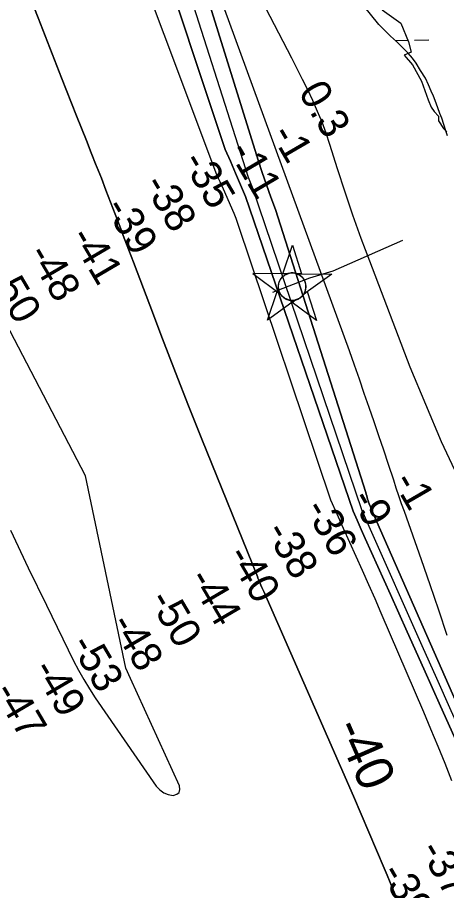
# Model space of a CAD drawing. Extents: x 3914892 to 3953151, y 242587 to 268572.
# Drawn here: x 3942793 to 3943744, y 249840 to 251778 of the extents above; entities that cross this region are included whole.
import ezdxf

# ---------------------------------------------------------------- set-up
doc = ezdxf.new("R2010")
doc.units = 0
for name, color, linetype in [('V-CHAN-NAID', 7, 'Continuous'), ('V-LEVE-TOET', 7, 'Continuous'), ('V-RIVR-EDGE', 7, 'Continuous'), ('V-RIVR-RANG', 7, 'Continuous'), ('V-TOPO-DPTH', 7, 'Continuous'), ('V-TOPO-MAJR', 7, 'Continuous'), ('V-TOPO-MAJR-IDEN', 7, 'Continuous'), ('V-TOPO-MINR', 7, 'Continuous'), ('V-TOPO-WATR', 7, 'Continuous'), ('V-WETL-SWMP', 7, 'Continuous')]:
    doc.layers.add(name, color=color, linetype=linetype)

msp = doc.modelspace()

# ---------------------------------------------------------------- linework, layer by layer
at = {"layer": 'V-CHAN-NAID'}
for points in [[(3943390.8, 251209), (3943381.2, 251209.1), (3943402.3, 251272.6), (3943422.6, 251208.8), (3943413, 251208.9), (3943411.4, 251209.4), (3943409.3, 251210.1), (3943407.3, 251210.5), (3943405.2, 251210.8), (3943404.1, 251210.9), (3943402.5, 251211), (3943400.8, 251211), (3943399.4, 251210.9), (3943397.5, 251210.7), (3943396.2, 251210.5), (3943394.4, 251210.1), (3943392.9, 251209.7), (3943391.8, 251209.4)], [(3943390.8, 251209), (3943314.3, 251209.6), (3943375.9, 251164.2), (3943374.8, 251166.1), (3943374, 251167.7), (3943373.1, 251169.7), (3943372.4, 251171.7), (3943372.1, 251173), (3943371.7, 251174.7), (3943371.5, 251176.1), (3943371.3, 251177.7), (3943371.2, 251179.4), (3943371.2, 251181), (3943371.3, 251183.1), (3943371.5, 251184.7), (3943371.8, 251186.9), (3943372.3, 251188.8), (3943372.9, 251190.7), (3943373.6, 251192.4), (3943374.3, 251194), (3943375.1, 251195.5), (3943376.2, 251197.3), (3943377.2, 251198.7), (3943378.2, 251200), (3943379.2, 251201.2), (3943380.5, 251202.5), (3943381.6, 251203.5), (3943383.3, 251204.9), (3943384.5, 251205.7), (3943386.2, 251206.8), (3943387.9, 251207.7), (3943389.4, 251208.4)], [(3943413, 251208.9), (3943489.5, 251208.3), (3943427.3, 251163.8), (3943428.2, 251165.3), (3943429.2, 251167.1), (3943429.9, 251168.7), (3943430.6, 251170.7), (3943431.2, 251172.5), (3943431.6, 251174.1), (3943431.9, 251176.1), (3943432.1, 251177.7), (3943432.2, 251179.9), (3943432.2, 251181.9), (3943432, 251184.2), (3943431.7, 251185.9), (3943431.3, 251188.2), (3943430.6, 251190.3), (3943429.9, 251192.3), (3943429.2, 251193.7), (3943428.2, 251195.6), (3943427.1, 251197.4), (3943425.9, 251199.1), (3943424.7, 251200.6), (3943423.4, 251202), (3943421.8, 251203.5), (3943420, 251204.9), (3943418.3, 251206.1), (3943416.5, 251207.2), (3943415, 251208)], [(3943409.2, 251150.9), (3943347, 251106.4), (3943368.2, 251169.8), (3943375.9, 251164.2), (3943376.5, 251163.2), (3943377.9, 251161.3), (3943379.1, 251159.9), (3943380.6, 251158.4), (3943382, 251157.2), (3943383.4, 251156), (3943384.8, 251155), (3943386.5, 251154), (3943388.2, 251153.1), (3943390, 251152.3), (3943391.5, 251151.7), (3943393.1, 251151.2), (3943395.3, 251150.6), (3943396.8, 251150.3), (3943398.9, 251150.1), (3943400.4, 251150), (3943402.3, 251149.9), (3943404, 251150), (3943405.7, 251150.2), (3943407.6, 251150.5)], [(3943427.3, 251163.8), (3943435.1, 251169.4), (3943455.3, 251105.6), (3943401.4, 251145.3), (3943409.2, 251150.9), (3943410.9, 251151.4), (3943412.5, 251151.9), (3943414.7, 251152.8), (3943416.4, 251153.7), (3943418.3, 251154.8), (3943420, 251156), (3943421.6, 251157.3), (3943422.9, 251158.5), (3943424.2, 251159.9), (3943425.4, 251161.3), (3943426.6, 251162.8)]]:
    msp.add_lwpolyline(points, close=True, dxfattribs=at)
msp.add_circle((3943401.7, 251180.5), 30.5, dxfattribs=at)
at = {"layer": 'V-LEVE-TOET'}
msp.add_lwpolyline([(3943646.5, 251283.2), (3943491.9, 251215.2), (3943439.9, 251199.1), (3943358.3, 251167.6)], dxfattribs=at)
at = {"layer": 'V-RIVR-EDGE'}
msp.add_lwpolyline([(3943600.9, 251794.9), (3943642.4, 251765.5), (3943659.8, 251724), (3943665.3, 251701.1), (3943650, 251694.6), (3943668.6, 251672.8), (3943688.2, 251636.8), (3943703.5, 251595.3), (3943710, 251578.9), (3943716.6, 251569.1), (3943726.4, 251559.3), (3943726.4, 251548.4), (3943737.3, 251532), (3943744.9, 251524.4)], dxfattribs=at)
at = {"layer": 'V-TOPO-DPTH'}
for points in [[(3944620.8, 248476), (3944296.7, 249247.2), (3943983.6, 250085.5), (3943808.9, 250673.8), (3943732.9, 250836.2), (3943663.5, 251001.9), (3943573.7, 251236.8), (3943554.7, 251287.8), (3943536.4, 251339), (3943519.1, 251390.6), (3943502.4, 251442.4), (3943485.5, 251496.3), (3943477.2, 251521.1), (3943468.2, 251545.7), (3943458.2, 251569.8), (3943447.5, 251593.7), (3943436.2, 251617.3), (3943424.7, 251640.8), (3943412.9, 251664.2), (3943401, 251687.5), (3943105.5, 252257.6)], [(3943134.6, 252077), (3943326, 251461.7), (3943335.1, 251434.1), (3943344.7, 251406.5), (3943354.7, 251379.1), (3943364.8, 251351.7), (3943565.3, 250723.3), (3943566.1, 250719.7), (3943567, 250716.1), (3943567.8, 250712.5), (3943568.8, 250709), (3943569.9, 250705.4), (3943571.1, 250702), (3943572.4, 250698.5), (3943577.5, 250686.1), (3943578.5, 250683.7), (3943579.5, 250681.4), (3943580.4, 250679.1), (3943581.5, 250676.8), (3943773.8, 250239.1)], [(3943134.6, 252077), (3943326, 251461.7), (3943335.1, 251434.1), (3943344.7, 251406.5), (3943354.7, 251379.1), (3943364.8, 251351.7), (3943565.3, 250723.3), (3943566.1, 250719.7), (3943567, 250716.1), (3943567.8, 250712.5), (3943568.8, 250709), (3943569.9, 250705.4), (3943571.1, 250702), (3943572.4, 250698.5), (3943577.5, 250686.1), (3943578.5, 250683.7), (3943579.5, 250681.4), (3943580.4, 250679.1), (3943581.5, 250676.8), (3943773.8, 250239.1)], [(3943756, 250083.5), (3943740.8, 250121.7), (3943725.3, 250159.8), (3943709.5, 250197.8), (3943693.5, 250235.6), (3943599.1, 250455.7), (3943585.5, 250487.2), (3943571.7, 250518.6), (3943557.6, 250550), (3943543.5, 250581.3), (3943529.2, 250612.5), (3943515.2, 250643.9), (3943501.3, 250675.3), (3943487.5, 250706.7), (3943281.1, 251320.5), (3943277.2, 251331.7), (3943272.8, 251342.7), (3943249.2, 251397), (3943245.7, 251405), (3943242.1, 251412.9), (3943238.6, 251420.8), (3943234.9, 251428.7), (3943001.1, 252053)], [(3943756, 250083.5), (3943740.8, 250121.7), (3943725.3, 250159.8), (3943709.5, 250197.8), (3943693.5, 250235.6), (3943599.1, 250455.7), (3943585.5, 250487.2), (3943571.7, 250518.6), (3943557.6, 250550), (3943543.5, 250581.3), (3943529.2, 250612.5), (3943515.2, 250643.9), (3943501.3, 250675.3), (3943487.5, 250706.7), (3943281.1, 251320.5), (3943277.2, 251331.7), (3943272.8, 251342.7), (3943249.2, 251397), (3943245.7, 251405), (3943242.1, 251412.9), (3943238.6, 251420.8), (3943234.9, 251428.7), (3943001.1, 252053)], [(3944118.2, 249216.8), (3943880.1, 249911.6), (3943873.7, 249926.8), (3943867.3, 249941.9), (3943860.8, 249957), (3943854.1, 249972), (3943767.3, 250166.8), (3943730.5, 250249.3), (3943693.6, 250331.8), (3943656.6, 250414.3), (3943619.6, 250496.7), (3943563.7, 250621.1), (3943554.6, 250641.4), (3943545.7, 250661.7), (3943536.9, 250682), (3943298.2, 251380.4), (3943287.2, 251406.6), (3943276.1, 251432.8), (3943264.8, 251458.9), (3943253.4, 251485), (3943092.2, 251970.5)], [(3943092.2, 251970.5), (3943253.4, 251485), (3943264.8, 251458.9), (3943276.1, 251432.8), (3943287.2, 251406.6), (3943298.2, 251380.4), (3943536.9, 250682), (3943545.7, 250661.7), (3943554.6, 250641.4), (3943563.7, 250621.1), (3943619.6, 250496.7), (3943656.6, 250414.3), (3943693.6, 250331.8), (3943730.5, 250249.3), (3943767.3, 250166.8), (3943854.1, 249972), (3943860.8, 249957), (3943867.3, 249941.9), (3943873.7, 249926.8), (3943880.1, 249911.6), (3944118.2, 249216.8)], [(3942812.6, 251843.9), (3942838.2, 251777.3), (3942864.1, 251710.9), (3942890.2, 251644.5), (3942923.7, 251559.7), (3942934.6, 251532.2), (3942945.5, 251504.7), (3942956.3, 251477.3), (3942967.2, 251449.8), (3942968, 251447.8), (3942978.5, 251421.3), (3942988.8, 251394.8), (3942999, 251368.2), (3943009.2, 251341.5), (3943019.3, 251314.9), (3943029.3, 251288.3), (3943039.4, 251261.6), (3943049.5, 251235), (3943085.7, 251139.1), (3943114.1, 251064.6), (3943142.9, 250990.2), (3943172.1, 250916), (3943201.6, 250841.9), (3943324.5, 250536.7), (3943325.8, 250533.4), (3943327.2, 250530.1), (3943327.8, 250528.5), (3943329.2, 250525.2), (3943329.9, 250523.6), (3943332.5, 250517.4), (3943334.6, 250512.7), (3943336.6, 250508), (3943338.7, 250503.3), (3943340.7, 250498.6), (3943537.4, 250048.9), (3943554.7, 250009.1), (3943571.9, 249969.3), (3943588.9, 249929.5), (3943605.8, 249889.6), (3943612.6, 249873.6), (3943626, 249841.6), (3943639.3, 249809.6)], [(3943639.3, 249809.6), (3943626, 249841.6), (3943612.6, 249873.6), (3943605.8, 249889.6), (3943588.9, 249929.5), (3943571.9, 249969.3), (3943554.7, 250009.1), (3943537.4, 250048.9), (3943340.7, 250498.6), (3943338.7, 250503.3), (3943336.6, 250508), (3943334.6, 250512.7), (3943332.5, 250517.4), (3943329.9, 250523.6), (3943329.2, 250525.2), (3943327.8, 250528.5), (3943327.2, 250530.1), (3943325.8, 250533.4), (3943324.5, 250536.7), (3943201.6, 250841.9), (3943172.1, 250916), (3943142.9, 250990.2), (3943114.1, 251064.6), (3943085.7, 251139.1), (3943049.5, 251235), (3943039.4, 251261.6), (3943029.3, 251288.3), (3943019.3, 251314.9), (3943009.2, 251341.5), (3942999, 251368.2), (3942988.8, 251394.8), (3942978.5, 251421.3), (3942968, 251447.8), (3942967.2, 251449.8), (3942956.3, 251477.3), (3942945.5, 251504.7), (3942934.6, 251532.2), (3942923.7, 251559.7), (3942890.2, 251644.5), (3942864.1, 251710.9), (3942838.2, 251777.3), (3942812.6, 251843.9)]]:
    msp.add_lwpolyline(points, dxfattribs=at)
at = {"layer": 'V-TOPO-MAJR'}
for points in [[(3943032.7, 250333.5), (3942943.1, 250760.2), (3942776.3, 251081.7), (3942764.3, 251103.8), (3942751.8, 251125.7), (3942738.5, 251147.1), (3942724.8, 251168.2), (3942547.7, 251429.9), (3942505.6, 251490), (3942462.3, 251549.2), (3942417.1, 251607.1), (3942370.7, 251664), (3942302.3, 251745.3), (3942289.2, 251760.9), (3942276.1, 251776.4), (3942262.9, 251791.9)], [(3942777, 250639.8), (3942816.5, 250556.3), (3942856.7, 250473), (3942916.9, 250350), (3942927.8, 250328.7), (3942939.4, 250307.9), (3942951.9, 250287.5), (3942965, 250267.6), (3943100.4, 250071.3), (3943108.1, 250063), (3943116.8, 250056.6), (3943126.9, 250052.8), (3943138, 250050.9), (3943145.7, 250053.5), (3943150.9, 250057.6), (3943152.7, 250064.1), (3943152.1, 250072.1), (3943043.2, 250310.8), (3943032.7, 250333.5)]]:
    msp.add_lwpolyline(points, dxfattribs=at)
at = {"layer": 'V-TOPO-MINR'}
for points in [[(3943745.5, 250406.1), (3943727, 250462.2), (3943707.9, 250518.1), (3943688.5, 250573.9), (3943650.6, 250681.1), (3943644.5, 250698.5), (3943638.5, 250715.9), (3943632.6, 250733.3), (3943626.8, 250750.7), (3943615.1, 250786), (3943604.6, 250817.6), (3943594, 250849.1), (3943583.3, 250880.6), (3943572.6, 250912.1), (3943561.7, 250943.6), (3943550.8, 250975), (3943539.7, 251006.4), (3943528.6, 251037.7), (3943087.7, 252247.7)], [(3943773.8, 250239.1), (3943581.5, 250676.8), (3943580.4, 250679.1), (3943579.5, 250681.4), (3943578.5, 250683.7), (3943577.5, 250686.1), (3943572.4, 250698.5), (3943571.1, 250702), (3943569.9, 250705.4), (3943568.8, 250709), (3943567.8, 250712.5), (3943567, 250716.1), (3943566.1, 250719.7), (3943565.3, 250723.3), (3943364.8, 251351.7), (3943354.7, 251379.1), (3943344.7, 251406.5), (3943335.1, 251434.1), (3943326, 251461.7), (3943134.6, 252077)], [(3943756, 250083.5), (3943740.8, 250121.7), (3943725.3, 250159.8), (3943709.5, 250197.8), (3943693.5, 250235.6), (3943599.1, 250455.7), (3943585.5, 250487.2), (3943571.7, 250518.6), (3943557.6, 250550), (3943543.5, 250581.3), (3943529.2, 250612.5), (3943515.2, 250643.9), (3943501.3, 250675.3), (3943487.5, 250706.7), (3943281.1, 251320.5), (3943277.2, 251331.7), (3943272.8, 251342.7), (3943249.2, 251397), (3943245.7, 251405), (3943242.1, 251412.9), (3943238.6, 251420.8), (3943234.9, 251428.7), (3943001.1, 252053)], [(3944118.2, 249216.8), (3943880.1, 249911.6), (3943873.7, 249926.8), (3943867.3, 249941.9), (3943860.8, 249957), (3943854.1, 249972), (3943767.3, 250166.8), (3943730.5, 250249.3), (3943693.6, 250331.8), (3943656.6, 250414.3), (3943619.6, 250496.7), (3943563.7, 250621.1), (3943554.6, 250641.4), (3943545.7, 250661.7), (3943536.9, 250682), (3943298.2, 251380.4), (3943287.2, 251406.6), (3943276.1, 251432.8), (3943264.8, 251458.9), (3943253.4, 251485), (3943092.2, 251970.5)], [(3944145.9, 249192), (3943903, 249904), (3943893.1, 249927.5), (3943883, 249951), (3943872.8, 249974.5), (3943862.4, 249997.8), (3943818.8, 250095), (3943786.6, 250166.9), (3943754.5, 250238.8), (3943722.4, 250310.8), (3943690.3, 250382.7), (3943572.2, 250648.2), (3943567.1, 250659.7), (3943562.1, 250671.3), (3943557.2, 250682.9), (3943313.6, 251401), (3943304.7, 251422.7), (3943149, 251911.8)], [(3943639.3, 249809.6), (3943626, 249841.6), (3943612.6, 249873.6), (3943605.8, 249889.6), (3943588.9, 249929.5), (3943571.9, 249969.3), (3943554.7, 250009.1), (3943537.4, 250048.9), (3943340.7, 250498.6), (3943338.7, 250503.3), (3943336.6, 250508), (3943334.6, 250512.7), (3943332.5, 250517.4), (3943329.9, 250523.6), (3943329.2, 250525.2), (3943327.8, 250528.5), (3943327.2, 250530.1), (3943325.8, 250533.4), (3943324.5, 250536.7), (3943201.6, 250841.9), (3943172.1, 250916), (3943142.9, 250990.2), (3943114.1, 251064.6), (3943085.7, 251139.1), (3943049.5, 251235), (3943039.4, 251261.6), (3943029.3, 251288.3), (3943019.3, 251314.9), (3943009.2, 251341.5), (3942999, 251368.2), (3942988.8, 251394.8), (3942978.5, 251421.3), (3942968, 251447.8), (3942967.2, 251449.8), (3942956.3, 251477.3), (3942945.5, 251504.7), (3942934.6, 251532.2), (3942923.7, 251559.7), (3942890.2, 251644.5), (3942864.1, 251710.9), (3942838.2, 251777.3), (3942812.6, 251843.9)]]:
    msp.add_lwpolyline(points, dxfattribs=at)
at = {"layer": 'V-TOPO-WATR'}
msp.add_lwpolyline([(3944620.8, 248476), (3944296.7, 249247.2), (3943983.6, 250085.5), (3943808.9, 250673.8), (3943732.9, 250836.2), (3943663.5, 251001.9), (3943573.7, 251236.8), (3943554.7, 251287.8), (3943536.4, 251339), (3943519.1, 251390.6), (3943502.4, 251442.4), (3943485.5, 251496.3), (3943477.2, 251521.1), (3943468.2, 251545.7), (3943458.2, 251569.8), (3943447.5, 251593.7), (3943436.2, 251617.3), (3943424.7, 251640.8), (3943412.9, 251664.2), (3943401, 251687.5), (3943105.5, 252257.6)], dxfattribs=at)
at = {"layer": 'V-WETL-SWMP'}
for p, q in [((3943593.9, 251762.3), (3943559.6, 251804.7)), ((3943606.3, 251750.1), (3943593.9, 251762.3)), ((3943620.1, 251736.4), (3943606.3, 251750.1)), ((3943632.9, 251724.8), (3943620.1, 251736.4)), ((3943630.4, 251727.1), (3943656.7, 251727.5)), ((3943647.2, 251710.9), (3943632.9, 251724.8)), ((3943672.7, 251727.8), (3943704.7, 251728.4)), ((3943658.6, 251699.1), (3943647.2, 251710.9)), ((3943668.3, 251687.6), (3943658.6, 251699.1)), ((3943676.5, 251677), (3943668.3, 251687.6)), ((3943686.2, 251660.8), (3943676.5, 251677)), ((3943697, 251643.1), (3943686.2, 251660.8)), ((3943704.1, 251628.5), (3943697, 251643.1)), ((3943710.3, 251614.5), (3943704.1, 251628.5)), ((3943715.2, 251603.4), (3943710.3, 251614.5)), ((3943721.2, 251587.6), (3943715.2, 251603.4)), ((3943729, 251565.1), (3943721.2, 251587.6)), ((3943733.3, 251554.6), (3943729, 251565.1)), ((3943738.3, 251540.2), (3943733.3, 251554.6)), ((3943742.8, 251526.6), (3943738.3, 251540.2)), ((3943746.3, 251515.3), (3943742.8, 251526.6))]:
    msp.add_line(p, q, dxfattribs=at)

# ---------------------------------------------------------------- texts
at = {"layer": 'V-RIVR-RANG'}
for s, rotation, p in [('0.3', 300.2183, (3943414.1, 251612.8)), ('-1', 300.2183, (3943353.1, 251518.9)), ('-11', 300.4994, (3943259, 251481.4)), ('-35', 300.4994, (3943155.9, 251459.2)), ('-38', 300.4994, (3943070.2, 251407.8)), ('-39', 300.4994, (3942984.3, 251356.6)), ('-41', 300.4994, (3942906.8, 251291)), ('-48', 300.4994, (3942813.2, 251253)), ('-50', 300.4994, (3942725.7, 251204.5)), ('-1', 300.1283, (3943623.4, 250748.1)), ('-9', 300.1283, (3943530.2, 250709.6)), ('-36', 300.4126, (3943427, 250687.3)), ('-38', 300.4126, (3943340.3, 250637.4)), ('-40', 300.4126, (3943255.7, 250584)), ('-44', 300.4126, (3943169.9, 250532.7)), ('-50', 300.4126, (3943081.9, 250485)), ('-48', 300.4126, (3942996.8, 250432.5)), ('-53', 300.4126, (3942908, 250386.2)), ('-49', 300.4126, (3942824.4, 250331)), ('-47', 300.4126, (3942737.8, 250281.1)), ('-37', 300.2615, (3943682.2, 249929.5)), ('-39', 300.2615, (3943595.9, 249878.9))]:
    msp.add_text(s, height=67, rotation=rotation, dxfattribs=at).set_placement(p)
at = {"layer": 'V-TOPO-MAJR-IDEN'}
msp.add_text('-40', height=83, rotation=293.6236, dxfattribs=at).set_placement((3943494, 250202.3))

doc.saveas('drawing.dxf')
